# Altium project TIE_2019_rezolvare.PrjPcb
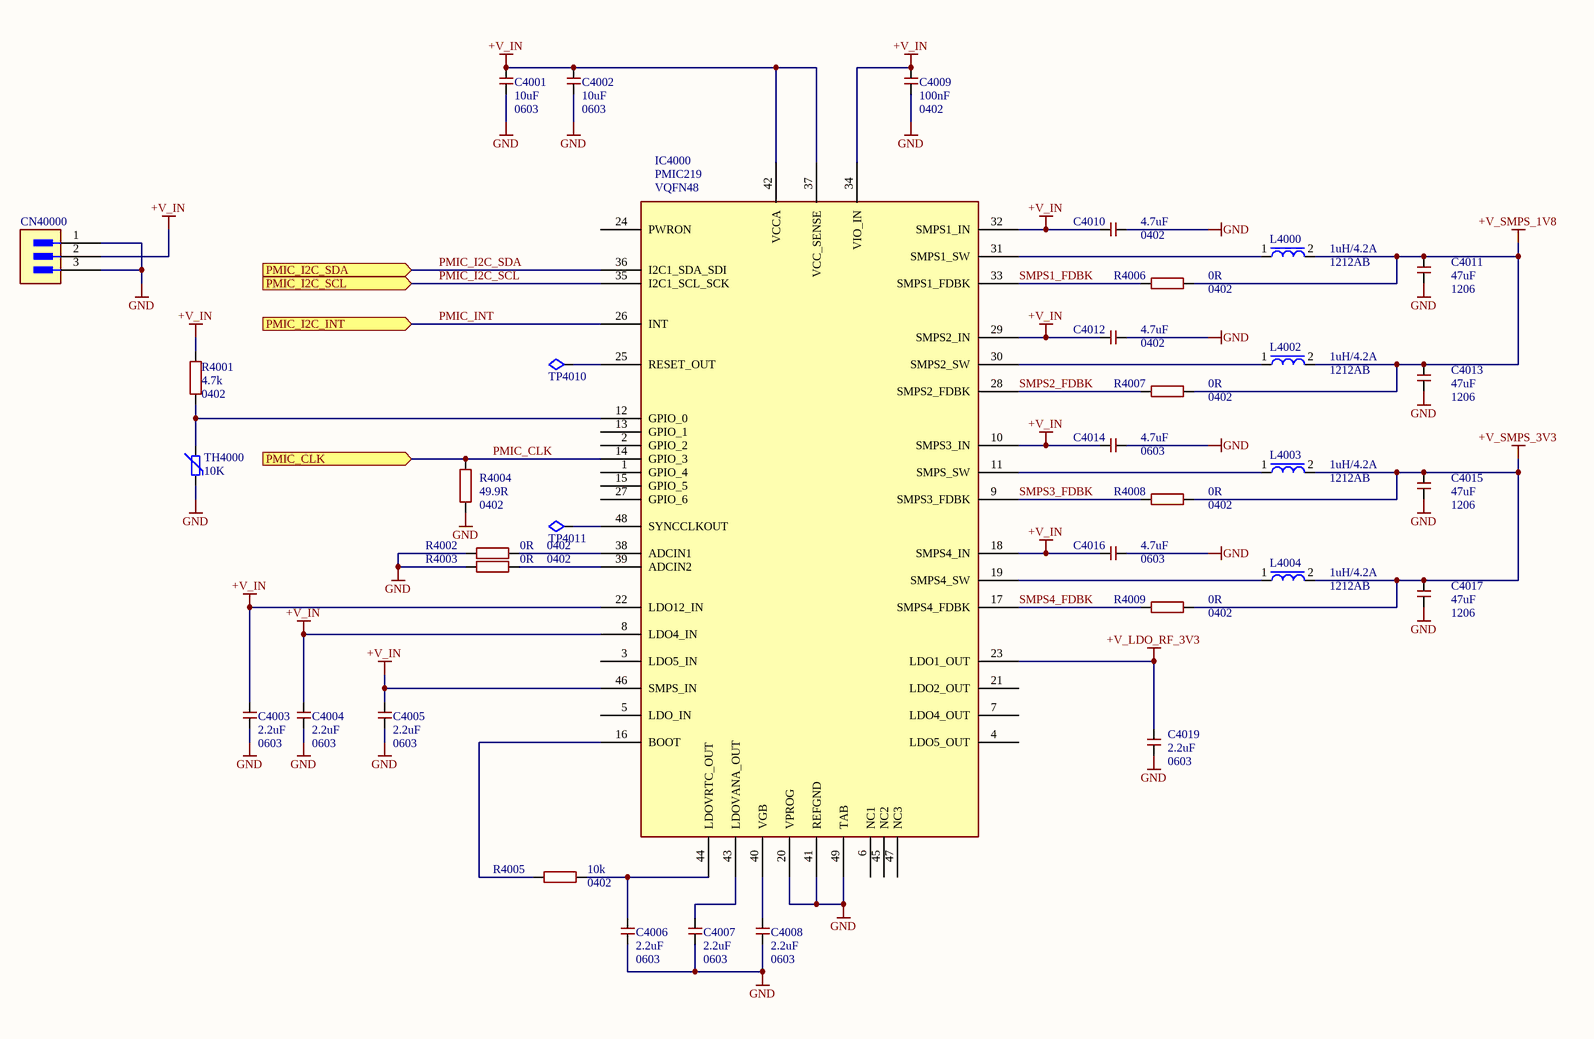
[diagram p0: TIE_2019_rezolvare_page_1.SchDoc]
2 sheets, 97 parts. Net scope: flat (ports and power ports of the same name join across sheets).
Board file: TIE2019_rezolvare.PcbDoc
Sheets:
  TIE_2019_rezolvare_page_1.SchDoc
  TIE_2019_rezolvare_page_2.SchDoc

## Sheet TIE_2019_rezolvare_page_1.SchDoc
size A3; SheetNumber: 1; SheetTotal: 2

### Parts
C4001  10uF  Footprint Name: 0603  [CAP0603]
C4002  10uF  Footprint Name: 0603  [CAP0603]
C4003  2.2uF  Footprint Name: 0603  [CAP0603]
C4004  2.2uF  Footprint Name: 0603  [CAP0603]
C4005  2.2uF  Footprint Name: 0603  [CAP0603]
C4006  2.2uF  Footprint Name: 0603  [CAP0603]
C4007  2.2uF  Footprint Name: 0603  [CAP0603]
C4008  2.2uF  Footprint Name: 0603  [CAP0603]
C4009  100nF  Footprint Name: 0402  [CAP0402]
C4010  4.7uF  Footprint Name: 0402  [CAP0402]
C4011  47uF  Footprint Name: 1206  [CAP1206]
C4012  4.7uF  Footprint Name: 0402  [CAP0402]
C4013  47uF  Footprint Name: 1206  [CAP1206]
C4014  4.7uF  Footprint Name: 0603  [CAP0603]
C4015  47uF  Footprint Name: 1206  [CAP1206]
C4016  4.7uF  Footprint Name: 0603  [CAP0603]
C4017  47uF  Footprint Name: 1206  [CAP1206]
C4019  2.2uF  Footprint Name: 0603  [CAP0603]
CN40000  Connector 1x3  [Conn1x03]  (value not drawn)
IC4000  PMIC219  Footprint: VQFN48  [48-QFN]
L4000  1uH/4.2A  Footprint: 1212AB  [L_1212AB]
L4002  1uH/4.2A  Footprint: 1212AB  [L_1212AB]
L4003  1uH/4.2A  Footprint: 1212AB  [L_1212AB]
L4004  1uH/4.2A  Footprint: 1212AB  [L_1212AB]
R4001  4.7k  Footprint Name: 0402  [RES0402]
R4002  0R  Footprint Name: 0402  [RES0402]
R4003  0R  Footprint Name: 0402  [RES0402]
R4004  49.9R  Footprint Name: 0402  [RES0402]
R4005  10k  Footprint Name: 0402  [RES0402]
R4006  0R  Footprint Name: 0402  [RES0402]
R4007  0R  Footprint Name: 0402  [RES0402]
R4008  0R  Footprint Name: 0402  [RES0402]
R4009  0R  Footprint Name: 0402  [RES0402]
TH4000  10K  [RES0402]
TP4010  TestPoint  [TestPoint_2019]  (value not drawn)  (no BOM)
TP4011  TestPoint  [TestPoint_2019]  (value not drawn)  (no BOM)

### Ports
PMIC_CLK (in, see TIE_2019_rezolvare_page_2[1B]), PMIC_I2C_INT (in, see TIE_2019_rezolvare_page_2[1B]), PMIC_I2C_SCL (in, see TIE_2019_rezolvare_page_2[1B]), PMIC_I2C_SDA (in, see TIE_2019_rezolvare_page_2[1B])

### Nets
+V_IN: C4001.2 C4002.2 C4003.2 C4004.1 C4005.1 C4009.2 C4010.1 C4012.1 C4014.1 C4016.1 CN40000.2 IC4000.8(LDO4_IN) IC4000.10(SMPS3_IN) IC4000.18(SMPS4_IN) IC4000.22(LDO12_IN) IC4000.29(SMPS2_IN) IC4000.32(SMPS1_IN) IC4000.34(VIO_IN) IC4000.37(VCC_SENSE) IC4000.42(VCCA) IC4000.46(SMPS_IN) R4001.2
+V_LDO_RF_3V3: C4019.2 IC4000.23(LDO1_OUT)
+V_SMPS_1V8: C4011.2 C4013.2 L4000.2 L4002.2 R4006.2 R4007.2
+V_SMPS_3V3: C4015.2 C4017.2 L4003.2 L4004.2 R4008.2 R4009.2
GND: C4001.1 C4002.1 C4003.1 C4004.2 C4005.2 C4006.1 C4007.1 C4008.1 C4009.1 C4010.2 C4011.1 C4012.2 C4013.1 C4014.2 C4015.1 C4016.2 C4017.1 C4019.1 CN40000.1 CN40000.3 IC4000.20(VPROG) IC4000.41(REFGND) IC4000.49(TAB) R4002.1 R4003.1 R4004.1 TH4000.1
PMIC_CLK: IC4000.14(GPIO_3) R4004.2 ; port PMIC_CLK
PMIC_I2C_SCL: IC4000.35(I2C1_SCL_SCK) ; port PMIC_I2C_SCL  [project net PMIC_I1C_SCL]
PMIC_I2C_SDA: IC4000.36(I2C1_SDA_SDI) ; port PMIC_I2C_SDA  [project net PMIC_I1C_SDA]
PMIC_INT: IC4000.26(INT) ; port PMIC_I2C_INT
SMPS1_FDBK: IC4000.33(SMPS1_FDBK) R4006.1
SMPS2_FDBK: IC4000.28(SMPS2_FDBK) R4007.1
SMPS3_FDBK: IC4000.9(SMPS3_FDBK) R4008.1
SMPS4_FDBK: IC4000.17(SMPS4_FDBK) R4009.1
NetC4006_2: C4006.2 IC4000.44(LDOVRTC_OUT) R4005.2
NetC4007_2: C4007.2 IC4000.43(LDOVANA_OUT)
NetC4008_2: C4008.2 IC4000.40(VGB)
NetIC4000_11: IC4000.11(SMPS_SW) L4003.1
NetIC4000_12: IC4000.12(GPIO_0) R4001.1 TH4000.2
NetIC4000_16: IC4000.16(BOOT) R4005.1
NetIC4000_19: IC4000.19(SMPS4_SW) L4004.1
NetIC4000_25: IC4000.25(RESET_OUT) TP4010.1
NetIC4000_30: IC4000.30(SMPS2_SW) L4002.1
NetIC4000_31: IC4000.31(SMPS1_SW) L4000.1
NetIC4000_38: IC4000.38(ADCIN1) R4002.2
NetIC4000_39: IC4000.39(ADCIN2) R4003.2
NetIC4000_48: IC4000.48(SYNCCLKOUT) TP4011.1

Not connected (* = marked no-connect by the designer): IC4000 1(GPIO_4) 2(GPIO_2) 3(LDO5_IN) 4(LDO5_OUT) 5(LDO_IN) 6(NC1) 7(LDO4_OUT) 13(GPIO_1) 15(GPIO_5) 21(LDO2_OUT) 24(PWRON) 27(GPIO_6) 45(NC2) 47(NC3)

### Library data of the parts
C4001 C4002 = C0603_10uF: CAP CER 10uF  SMD 0603; Manufacturer: Murata; Manufacturer Part Number: GJM1555C1H100JB01D
C4003-C4008 C4019 = C0603_2.2uF: CAP CER 2.2uF  SMD 0603; Manufacturer: Murata; Manufacturer Part Number: GJM1555C1H100JB01D
C4009 = C0402_100nF: CAP CER 100nF SMD 0402; Manufacturer: Murata; Manufacturer Part Number: GJM1555C1H100JB01D; Parameter 1: 50V
C4010 C4012 = C0402_4.7uF: CAP CER 4.7upF SMD 0402; Manufacturer: Murata; Manufacturer Part Number: GJM1555C1H100JB01D; Parameter 1: 50V
C4011 C4013 C4015 C4017 = C1206_47uF: CAP CER 47uF  SMD 1206; Manufacturer: Murata; Manufacturer Part Number: GJM1555C1H100JB01D
C4014 C4016 = C0603_4.7uF: CAP CER 4.7uF  SMD 0603; Manufacturer: Murata; Manufacturer Part Number: GJM1555C1H100JB01D
L4000 L4002-L4004 = IHLP1212AB
R4001 = R0402_4.7k: RES TKF 4.7k SMD 0402; Manufacturer: TE Connectivity; Manufacturer Part Number: CRG0402F10K; Tolerance: 1%
R4002 R4003 R4006-R4009 = R0402_0R: RES TKF 0R  SMD 0402; Manufacturer: TE Connectivity; Manufacturer Part Number: CRG0402F10K; Tolerance: 1%
R4004 = R0402_49.9R: RES TKF 49.9R SMD 0402; Manufacturer: TE Connectivity; Manufacturer Part Number: CRG0402F10K; Tolerance: 1%
R4005 = R0402_10k: RES TKF 10k  SMD 0402; Manufacturer: TE Connectivity; Manufacturer Part Number: CRG0402F10K; Tolerance: 1%
TH4000 = Thermistor: THERMISTOR 10K OHM  0402
TP4010 TP4011 = TestPoint: SMD test point; Manufacturer: NA; .Checked_PCB: AI; .Creator: RV

## Sheet TIE_2019_rezolvare_page_2.SchDoc
size A3; SheetNumber: 2; SheetTotal: 2
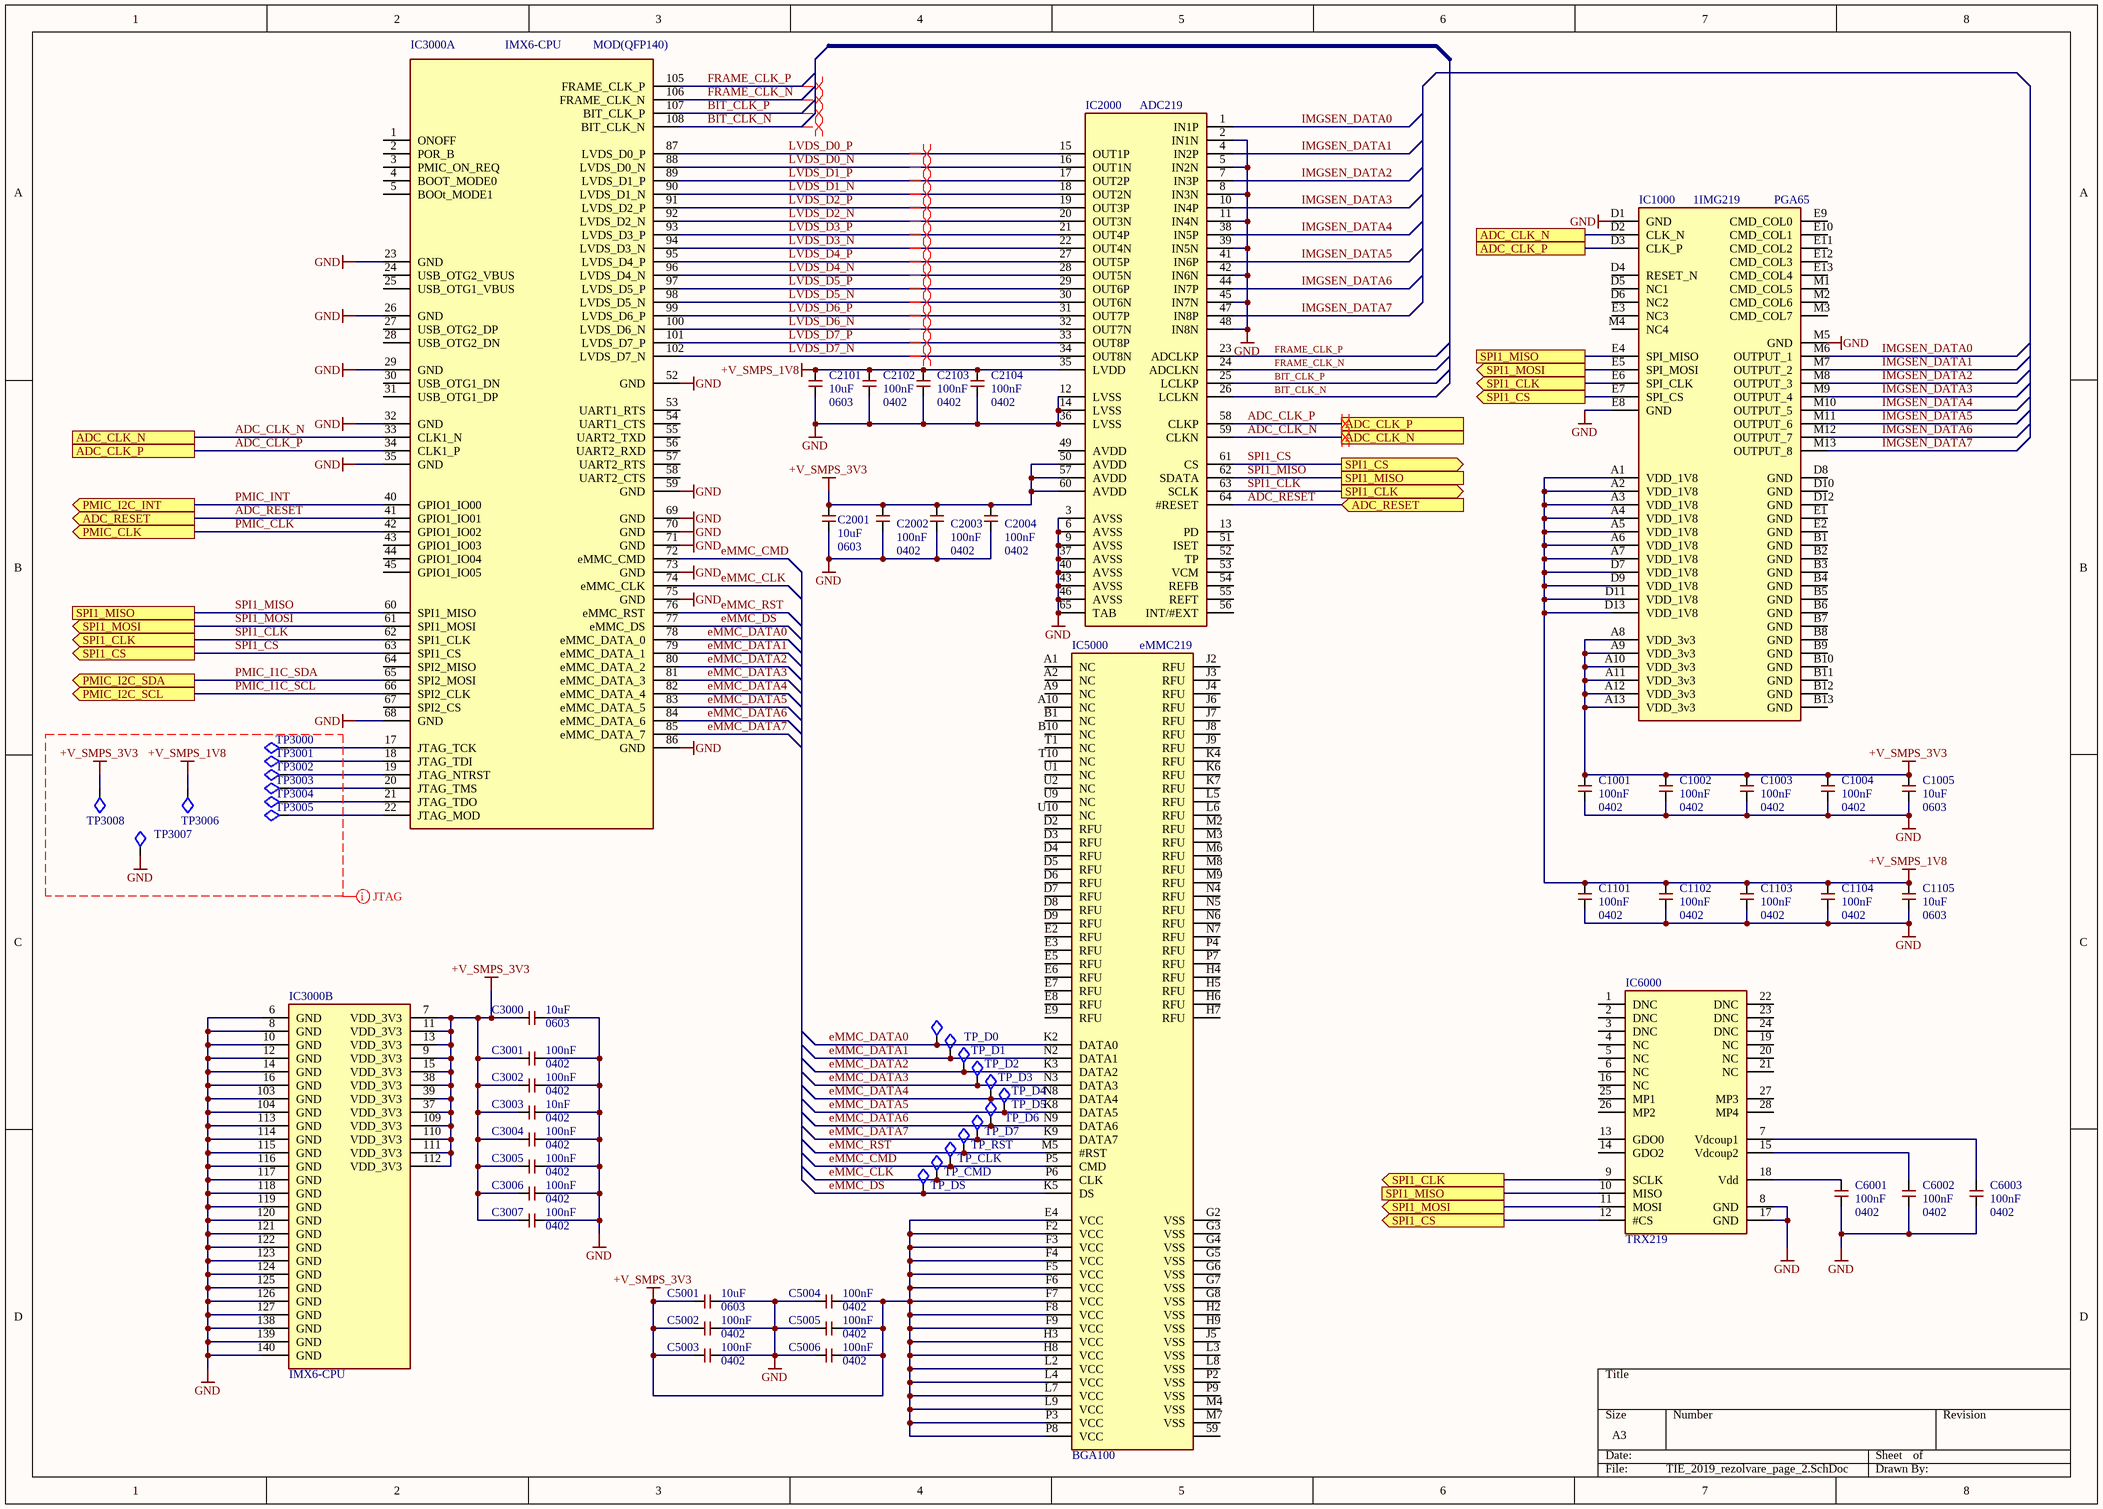
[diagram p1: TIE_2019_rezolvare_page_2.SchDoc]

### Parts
C1001  100nF  Footprint Name: 0402  [CAP0402]
C1002  100nF  Footprint Name: 0402  [CAP0402]
C1003  100nF  Footprint Name: 0402  [CAP0402]
C1004  100nF  Footprint Name: 0402  [CAP0402]
C1005  10uF  Footprint Name: 0603  [CAP0603]
C1101  100nF  Footprint Name: 0402  [CAP0402]
C1102  100nF  Footprint Name: 0402  [CAP0402]
C1103  100nF  Footprint Name: 0402  [CAP0402]
C1104  100nF  Footprint Name: 0402  [CAP0402]
C1105  10uF  Footprint Name: 0603  [CAP0603]
C2001  10uF  Footprint Name: 0603  [CAP0603]
C2002  100nF  Footprint Name: 0402  [CAP0402]
C2003  100nF  Footprint Name: 0402  [CAP0402]
C2004  100nF  Footprint Name: 0402  [CAP0402]
C2101  10uF  Footprint Name: 0603  [CAP0603]
C2102  100nF  Footprint Name: 0402  [CAP0402]
C2103  100nF  Footprint Name: 0402  [CAP0402]
C2104  100nF  Footprint Name: 0402  [CAP0402]
C3000  10uF  Footprint Name: 0603  [CAP0603]
C3001  100nF  Footprint Name: 0402  [CAP0402]
C3002  100nF  Footprint Name: 0402  [CAP0402]
C3003  10nF  Footprint Name: 0402  [CAP0402]
C3004  100nF  Footprint Name: 0402  [CAP0402]
C3005  100nF  Footprint Name: 0402  [CAP0402]
C3006  100nF  Footprint Name: 0402  [CAP0402]
C3007  100nF  Footprint Name: 0402  [CAP0402]
C5001  10uF  Footprint Name: 0603  [CAP0603]
C5002  100nF  Footprint Name: 0402  [CAP0402]
C5003  100nF  Footprint Name: 0402  [CAP0402]
C5004  100nF  Footprint Name: 0402  [CAP0402]
C5005  100nF  Footprint Name: 0402  [CAP0402]
C5006  100nF  Footprint Name: 0402  [CAP0402]
C6001  100nF  Footprint Name: 0402  [CAP0402]
C6002  100nF  Footprint Name: 0402  [CAP0402]
C6003  100nF  Footprint Name: 0402  [CAP0402]
IC1000  PGA65  [PGAx13]
IC2000  ADC219  [QFN64]
IC3000  IMX6-CPU  Footprint: MOD(QFP140)  [IMX6-SoM]  (parts A,B of 2)
IC5000  eMMC219  [BGA100]
IC6000  TRX219  [A1101R09C00GM]
TP3000  TestPoint  [TestPoint_2019]  (value not drawn)  (no BOM)
TP3001  TestPoint  [TestPoint_2019]  (value not drawn)  (no BOM)
TP3002  TestPoint  [TestPoint_2019]  (value not drawn)  (no BOM)
TP3003  TestPoint  [TestPoint_2019]  (value not drawn)  (no BOM)
TP3004  TestPoint  [TestPoint_2019]  (value not drawn)  (no BOM)
TP3005  TestPoint  [TestPoint_2019]  (value not drawn)  (no BOM)
TP3006  TestPoint  [TestPoint_2019]  (value not drawn)  (no BOM)
TP3007  TestPoint  [TestPoint_2019]  (value not drawn)  (no BOM)
TP3008  TestPoint  [TestPoint_2019]  (value not drawn)  (no BOM)
TP_CLK  TestPoint  [TestPoint_2019]  (value not drawn)  (no BOM)
TP_CMD  TestPoint  [TestPoint_2019]  (value not drawn)  (no BOM)
TP_D0  TestPoint  [TestPoint_2019]  (value not drawn)  (no BOM)
TP_D1  TestPoint  [TestPoint_2019]  (value not drawn)  (no BOM)
TP_D2  TestPoint  [TestPoint_2019]  (value not drawn)  (no BOM)
TP_D3  TestPoint  [TestPoint_2019]  (value not drawn)  (no BOM)
TP_D4  TestPoint  [TestPoint_2019]  (value not drawn)  (no BOM)
TP_D5  TestPoint  [TestPoint_2019]  (value not drawn)  (no BOM)
TP_D6  TestPoint  [TestPoint_2019]  (value not drawn)  (no BOM)
TP_D7  TestPoint  [TestPoint_2019]  (value not drawn)  (no BOM)
TP_DS  TestPoint  [TestPoint_2019]  (value not drawn)  (no BOM)
TP_RST  TestPoint  [TestPoint_2019]  (value not drawn)  (no BOM)

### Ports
ADC_CLK_N (see TIE_2019_rezolvare_page_2[1B], TIE_2019_rezolvare_page_2[6A]), ADC_CLK_N (see TIE_2019_rezolvare_page_2[1B], TIE_2019_rezolvare_page_2[6B]), ADC_CLK_N (see TIE_2019_rezolvare_page_2[6A], TIE_2019_rezolvare_page_2[6B]), ADC_CLK_P (see TIE_2019_rezolvare_page_2[1B], TIE_2019_rezolvare_page_2[6A]), ADC_CLK_P (see TIE_2019_rezolvare_page_2[1B], TIE_2019_rezolvare_page_2[6B]), ADC_CLK_P (see TIE_2019_rezolvare_page_2[6A], TIE_2019_rezolvare_page_2[6B]), ADC_RESET (in, see TIE_2019_rezolvare_page_2[1B]), ADC_RESET (out, see TIE_2019_rezolvare_page_2[6B]), PMIC_CLK (out, see TIE_2019_rezolvare_page_1[2B]), PMIC_I2C_INT (out, see TIE_2019_rezolvare_page_1[2B]), PMIC_I2C_SCL (out, see TIE_2019_rezolvare_page_1[2B]), PMIC_I2C_SDA (out, see TIE_2019_rezolvare_page_1[2B]), SPI1_CLK (out, see TIE_2019_rezolvare_page_2[1B], TIE_2019_rezolvare_page_2[6B]), SPI1_CLK (out, see TIE_2019_rezolvare_page_2[1B], TIE_2019_rezolvare_page_2[6B], TIE_2019_rezolvare_page_2[6D]), SPI1_CLK (out, see TIE_2019_rezolvare_page_2[6B], TIE_2019_rezolvare_page_2[6D]), SPI1_CS (out, see TIE_2019_rezolvare_page_2[1B], TIE_2019_rezolvare_page_2[6B]), SPI1_CS (out, see TIE_2019_rezolvare_page_2[1B], TIE_2019_rezolvare_page_2[6B], TIE_2019_rezolvare_page_2[6D]), SPI1_CS (out, see TIE_2019_rezolvare_page_2[6B], TIE_2019_rezolvare_page_2[6D]), SPI1_MISO (see TIE_2019_rezolvare_page_2[1B], TIE_2019_rezolvare_page_2[6A], TIE_2019_rezolvare_page_2[6B]), SPI1_MISO (see TIE_2019_rezolvare_page_2[1B], TIE_2019_rezolvare_page_2[6A], TIE_2019_rezolvare_page_2[6D]), SPI1_MISO (see TIE_2019_rezolvare_page_2[1B], TIE_2019_rezolvare_page_2[6B], TIE_2019_rezolvare_page_2[6D]), SPI1_MISO (see TIE_2019_rezolvare_page_2[6A], TIE_2019_rezolvare_page_2[6B], TIE_2019_rezolvare_page_2[6D]), SPI1_MOSI (out, see TIE_2019_rezolvare_page_2[1B], TIE_2019_rezolvare_page_2[6A]), SPI1_MOSI (out, see TIE_2019_rezolvare_page_2[1B], TIE_2019_rezolvare_page_2[6D]), SPI1_MOSI (out, see TIE_2019_rezolvare_page_2[6A], TIE_2019_rezolvare_page_2[6D])

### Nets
+V_SMPS_1V8: C1101.2 C1102.2 C1103.2 C1104.2 C1105.2 C2101.2 C2102.2 C2103.2 C2104.2 IC1000.A1(VDD_1V8) IC1000.A2(VDD_1V8) IC1000.A3(VDD_1V8) IC1000.A4(VDD_1V8) IC1000.A5(VDD_1V8) IC1000.A6(VDD_1V8) IC1000.A7(VDD_1V8) IC1000.D7(VDD_1V8) IC1000.D9(VDD_1V8) IC1000.D11(VDD_1V8) IC1000.D13(VDD_1V8) IC2000.35(LVDD) TP3006.1
+V_SMPS_3V3: C1001.2 C1002.2 C1003.2 C1004.2 C1005.2 C2001.2 C2002.2 C2003.2 C2004.2 C3000.1 C3001.1 C3002.1 C3003.1 C3004.1 C3005.1 C3006.1 C3007.1 C5001.1 C5002.1 C5003.1 C5004.2 C5005.2 C5006.2 IC1000.A8(VDD_3v3) IC1000.A9(VDD_3v3) IC1000.A10(VDD_3v3) IC1000.A11(VDD_3v3) IC1000.A12(VDD_3v3) IC1000.A13(VDD_3v3) IC2000.50(AVDD) IC2000.57(AVDD) IC2000.60(AVDD) IC3000.7(VDD_3V3) IC3000.9(VDD_3V3) IC3000.11(VDD_3V3) IC3000.13(VDD_3V3) IC3000.15(VDD_3V3) IC3000.37(VDD_3V3) IC3000.38(VDD_3V3) IC3000.39(VDD_3V3) IC3000.109(VDD_3V3) IC3000.110(VDD_3V3) IC3000.111(VDD_3V3) IC3000.112(VDD_3V3) IC5000.E4(VCC) IC5000.F2(VCC) IC5000.F3(VCC) IC5000.F4(VCC) IC5000.F5(VCC) IC5000.F6(VCC) IC5000.F7(VCC) IC5000.F8(VCC) IC5000.F9(VCC) IC5000.H3(VCC) IC5000.H8(VCC) IC5000.L2(VCC) IC5000.L4(VCC) IC5000.L7(VCC) IC5000.L9(VCC) IC5000.P3(VCC) IC5000.P8(VCC) TP3008.1
GND: C1001.1 C1002.1 C1003.1 C1004.1 C1005.1 C1101.1 C1102.1 C1103.1 C1104.1 C1105.1 C2001.1 C2002.1 C2003.1 C2004.1 C2101.1 C2102.1 C2103.1 C2104.1 C3000.2 C3001.2 C3002.2 C3003.2 C3004.2 C3005.2 C3006.2 C3007.2 C5001.2 C5002.2 C5003.2 C5004.1 C5005.1 C5006.1 C6001.1 C6002.1 C6003.1 IC1000.D1(GND) IC1000.E8(GND) IC1000.M5(GND) IC2000.2(IN1N) IC2000.3(AVSS) IC2000.5(IN2N) IC2000.6(AVSS) IC2000.8(IN3N) IC2000.9(AVSS) IC2000.11(IN4N) IC2000.12(LVSS) IC2000.14(LVSS) IC2000.36(LVSS) IC2000.37(AVSS) IC2000.39(IN5N) IC2000.40(AVSS) IC2000.42(IN6N) IC2000.43(AVSS) IC2000.45(IN7N) IC2000.46(AVSS) IC2000.48(IN8N) IC2000.65(TAB) IC3000.6(GND) IC3000.8(GND) IC3000.10(GND) IC3000.12(GND) IC3000.14(GND) IC3000.16(GND) IC3000.23(GND) IC3000.26(GND) IC3000.29(GND) IC3000.32(GND) IC3000.35(GND) IC3000.52(GND) IC3000.59(GND) IC3000.68(GND) IC3000.69(GND) IC3000.70(GND) IC3000.71(GND) IC3000.73(GND) IC3000.75(GND) IC3000.86(GND) IC3000.103(GND) IC3000.104(GND) IC3000.113(GND) IC3000.114(GND) IC3000.115(GND) IC3000.116(GND) IC3000.117(GND) IC3000.118(GND) IC3000.119(GND) IC3000.120(GND) IC3000.121(GND) IC3000.122(GND) IC3000.123(GND) IC3000.124(GND) IC3000.125(GND) IC3000.126(GND) IC3000.127(GND) IC3000.138(GND) IC3000.139(GND) IC3000.140(GND) IC6000.8(GND) IC6000.17(GND) TP3007.1
ADC_CLK_N: IC1000.D2(CLK_N) IC2000.59(CLKN) IC3000.33(CLK1_N) ; port ADC_CLK_N
ADC_CLK_P: IC1000.D3(CLK_P) IC2000.58(CLKP) IC3000.34(CLK1_P) ; port ADC_CLK_P
ADC_RESET: IC2000.64(#RESET) IC3000.41(GPIO1_IO01) ; port ADC_RESET
BIT_CLK_N: IC2000.26(LCLKN) IC3000.108(BIT_CLK_N)
BIT_CLK_P: IC2000.25(LCLKP) IC3000.107(BIT_CLK_P)
eMMC_CLK: IC3000.74(eMMC_CLK) IC5000.P6(CLK) TP_CMD.1
eMMC_CMD: IC3000.72(eMMC_CMD) IC5000.P5(CMD) TP_CLK.1
eMMC_DATA0: IC3000.78(eMMC_DATA_0) IC5000.K2(DATA0) TP_D0.1
eMMC_DATA1: IC3000.79(eMMC_DATA_1) IC5000.N2(DATA1) TP_D1.1
eMMC_DATA2: IC3000.80(eMMC_DATA_2) IC5000.K3(DATA2) TP_D2.1
eMMC_DATA3: IC3000.81(eMMC_DATA_3) IC5000.N3(DATA3) TP_D3.1
eMMC_DATA4: IC3000.82(eMMC_DATA_4) IC5000.N8(DATA4) TP_D4.1
eMMC_DATA5: IC3000.83(eMMC_DATA_5) IC5000.K8(DATA5) TP_D5.1
eMMC_DATA6: IC3000.84(eMMC_DATA_6) IC5000.N9(DATA6) TP_D6.1
eMMC_DATA7: IC3000.85(eMMC_DATA_7) IC5000.K9(DATA7) TP_D7.1
eMMC_DS: IC3000.77(eMMC_DS) IC5000.K5(DS) TP_DS.1
eMMC_RST: IC3000.76(eMMC_RST) IC5000.M5(#RST) TP_RST.1
FRAME_CLK_N: IC2000.24(ADCLKN) IC3000.106(FRAME_CLK_N)
FRAME_CLK_P: IC2000.23(ADCLKP) IC3000.105(FRAME_CLK_P)
IMGSEN_DATA0: IC1000.M6(OUTPUT_1) IC2000.1(IN1P)
IMGSEN_DATA1: IC1000.M7(OUTPUT_2) IC2000.4(IN2P)
IMGSEN_DATA2: IC1000.M8(OUTPUT_3) IC2000.7(IN3P)
IMGSEN_DATA3: IC1000.M9(OUTPUT_4) IC2000.10(IN4P)
IMGSEN_DATA4: IC1000.M10(OUTPUT_5) IC2000.38(IN5P)
IMGSEN_DATA5: IC1000.M11(OUTPUT_6) IC2000.41(IN6P)
IMGSEN_DATA6: IC1000.M12(OUTPUT_7) IC2000.44(IN7P)
IMGSEN_DATA7: IC1000.M13(OUTPUT_8) IC2000.47(IN8P)
LVDS_D0_N: IC2000.16(OUT1N) IC3000.88(LVDS_D0_N)
LVDS_D0_P: IC2000.15(OUT1P) IC3000.87(LVDS_D0_P)
LVDS_D1_N: IC2000.18(OUT2N) IC3000.90(LVDS_D1_N)
LVDS_D1_P: IC2000.17(OUT2P) IC3000.89(LVDS_D1_P)
LVDS_D2_N: IC2000.20(OUT3N) IC3000.92(LVDS_D2_N)
LVDS_D2_P: IC2000.19(OUT3P) IC3000.91(LVDS_D2_P)
LVDS_D3_N: IC2000.22(OUT4N) IC3000.94(LVDS_D3_N)
LVDS_D3_P: IC2000.21(OUT4P) IC3000.93(LVDS_D3_P)
LVDS_D4_N: IC2000.28(OUT5N) IC3000.96(LVDS_D4_N)
LVDS_D4_P: IC2000.27(OUT5P) IC3000.95(LVDS_D4_P)
LVDS_D5_N: IC2000.30(OUT6N) IC3000.98(LVDS_D5_N)
LVDS_D5_P: IC2000.29(OUT6P) IC3000.97(LVDS_D5_P)
LVDS_D6_N: IC2000.32(OUT7N) IC3000.100(LVDS_D6_N)
LVDS_D6_P: IC2000.31(OUT7P) IC3000.99(LVDS_D6_P)
LVDS_D7_N: IC2000.34(OUT8N) IC3000.102(LVDS_D7_N)
LVDS_D7_P: IC2000.33(OUT8P) IC3000.101(LVDS_D7_P)
PMIC_CLK: IC3000.42(GPIO1_IO02) ; port PMIC_CLK
PMIC_I1C_SCL: IC3000.66(SPI2_CLK) ; port PMIC_I2C_SCL
PMIC_I1C_SDA: IC3000.65(SPI2_MOSI) ; port PMIC_I2C_SDA
PMIC_INT: IC3000.40(GPIO1_IO00) ; port PMIC_I2C_INT
SPI1_CLK: IC1000.E6(SPI_CLK) IC2000.63(SCLK) IC3000.62(SPI1_CLK) IC6000.9(SCLK) ; port SPI1_CLK
SPI1_CS: IC1000.E7(SPI_CS) IC2000.61(CS) IC3000.63(SPI1_CS) IC6000.12(#CS) ; port SPI1_CS
SPI1_MISO: IC1000.E4(SPI_MISO) IC2000.62(SDATA) IC3000.60(SPI1_MISO) IC6000.10(MISO) ; port SPI1_MISO
SPI1_MOSI: IC1000.E5(SPI_MOSI) IC3000.61(SPI1_MOSI) IC6000.11(MOSI) ; port SPI1_MOSI
NetC6001_2: C6001.2 IC6000.18(Vdd)
NetC6002_2: C6002.2 IC6000.15(Vdcoup2)
NetC6003_2: C6003.2 IC6000.7(Vdcoup1)
NetIC3000_17: IC3000.17(JTAG_TCK) TP3000.1
NetIC3000_18: IC3000.18(JTAG_TDI) TP3001.1
NetIC3000_19: IC3000.19(JTAG_NTRST) TP3002.1
NetIC3000_20: IC3000.20(JTAG_TMS) TP3003.1
NetIC3000_21: IC3000.21(JTAG_TDO) TP3004.1
NetIC3000_22: IC3000.22(JTAG_MOD) TP3005.1

Not connected (* = marked no-connect by the designer): IC1000 B1(GND) B2(GND) B3(GND) B4(GND) B5(GND) B6(GND) B7(GND) B8(GND) B9(GND) B10(GND) B11(GND) B12(GND) B13(GND) D4(RESET_N) D5(NC1) D6(NC2) D8(GND) D10(GND) D12(GND) E1(GND) E2(GND) E3(NC3) E9(CMD_COL0) E10(CMD_COL1) E11(CMD_COL2) E12(CMD_COL3) E13(CMD_COL4) M1(CMD_COL5) M2(CMD_COL6) M3(CMD_COL7) M4(NC4); IC2000 13(PD) 49(AVDD) 51(ISET) 52(TP) 53(VCM) 54(REFB) 55(REFT) 56(INT/#EXT); IC3000 1(ONOFF) 2(POR_B) 3(PMIC_ON_REQ) 4(BOOT_MODE0) 5(BOOt_MODE1) 24(USB_OTG2_VBUS) 25(USB_OTG1_VBUS) 27(USB_OTG2_DP) 28(USB_OTG2_DN) 30(USB_OTG1_DN) 31(USB_OTG1_DP) 43(GPIO1_IO03) 44(GPIO1_IO04) 45(GPIO1_IO05) 53(UART1_RTS) 54(UART1_CTS) 55(UART2_TXD) 56(UART2_RXD) 57(UART2_RTS) 58(UART2_CTS) 64(SPI2_MISO) 67(SPI2_CS); IC5000 59 A1(NC) A2(NC) A9(NC) A10(NC) B1(NC) B10(NC) D2(RFU) D3(RFU) D4(RFU) D5(RFU) D6(RFU) D7(RFU) D8(RFU) D9(RFU) E2(RFU) E3(RFU) E5(RFU) E6(RFU) E7(RFU) E8(RFU) E9(RFU) G2(VSS) G3(VSS) G4(VSS) G5(VSS) G6(VSS) G7(VSS) G8(VSS) H2(VSS) H4(RFU) H5(RFU) H6(RFU) H7(RFU) H9(VSS) J2(RFU) J3(RFU) J4(RFU) J5(VSS) J6(RFU) J7(RFU) J8(RFU) J9(RFU) K4(RFU) K6(RFU) K7(RFU) L3(VSS) L5(RFU) L6(RFU) L8(VSS) M2(RFU) M3(RFU) M4(VSS) M6(RFU) M7(VSS) M8(RFU) M9(RFU) N4(RFU) N5(RFU) N6(RFU) N7(RFU) P2(VSS) P4(RFU) P7(RFU) P9(VSS) T1(NC) T10(NC) U1(NC) U2(NC) U9(NC) U10(NC); IC6000 1(DNC) 2(DNC) 3(DNC) 4(NC) 5(NC) 6(NC) 13(GDO0) 14(GDO2) 16(NC) 19(NC) 20(NC) 21(NC) 22(DNC) 23(DNC) 24(DNC) 25(MP1) 26(MP2) 27(MP3) 28(MP4)

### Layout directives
mark named JTAG: +V_SMPS_1V8, +V_SMPS_3V3, GND
differential pair: ADC_CLK_N, ADC_CLK_P, BIT_CLK_N, BIT_CLK_P, FRAME_CLK_N, FRAME_CLK_P, LVDS_D0_N, LVDS_D0_P, LVDS_D1_N, LVDS_D1_P, LVDS_D2_N, LVDS_D2_P, LVDS_D3_N, LVDS_D3_P, LVDS_D4_N, LVDS_D4_P, LVDS_D5_N, LVDS_D5_P, LVDS_D6_N, LVDS_D6_P, LVDS_D7_N, LVDS_D7_P

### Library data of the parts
C1001-C1004 C1101-C1104 C2002-C2004 C2102-C2104 C3001 C3002 C3004-C3007 C5002-C5006 C6001-C6003 = C0402_100nF: as C4009 on sheet TIE_2019_rezolvare_page_1
C1005 C1105 C2001 C2101 C3000 C5001 = C0603_10uF: as C4001 on sheet TIE_2019_rezolvare_page_1
C3003 = C0402_10nF: CAP CER 10nF SMD 0402; Manufacturer: Murata; Manufacturer Part Number: GJM1555C1H100JB01D; Parameter 1: 50V
IC1000 = 1IMG219
IC3000 = IMX6-CPU: 528MHz NXP i.MX 6UL/6ULL ARM Cortex-A7 Processors
IC5000 = eMMC219: BGA100
IC6000 = TRX219: MOD26
TP3000-TP3008 TP_CLK TP_CMD TP_D0-TP_D7 TP_DS TP_RST = TestPoint: as TP4010 on sheet TIE_2019_rezolvare_page_1

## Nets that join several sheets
+V_SMPS_1V8: TIE_2019_rezolvare_page_1 (6 pins), TIE_2019_rezolvare_page_2 (22 pins)
+V_SMPS_3V3: TIE_2019_rezolvare_page_1 (6 pins), TIE_2019_rezolvare_page_2 (62 pins)
GND: TIE_2019_rezolvare_page_1 (27 pins), TIE_2019_rezolvare_page_2 (100 pins)
PMIC_CLK: TIE_2019_rezolvare_page_1 (IC4000.14 R4004.2), TIE_2019_rezolvare_page_2 (IC3000.42)
PMIC_I1C_SCL: TIE_2019_rezolvare_page_1 (IC4000.35), TIE_2019_rezolvare_page_2 (IC3000.66)
PMIC_I1C_SDA: TIE_2019_rezolvare_page_1 (IC4000.36), TIE_2019_rezolvare_page_2 (IC3000.65)
PMIC_INT: TIE_2019_rezolvare_page_1 (IC4000.26), TIE_2019_rezolvare_page_2 (IC3000.40)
